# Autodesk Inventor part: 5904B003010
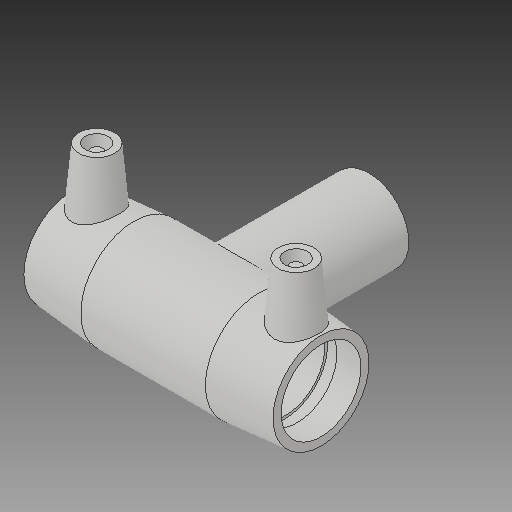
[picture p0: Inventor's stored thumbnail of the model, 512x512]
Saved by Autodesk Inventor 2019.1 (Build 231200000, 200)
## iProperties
Created: 2017-06
Part Number: 5904B003010
Material: Generic
Description: PLASSON TEE 1''IPS
Document SubType Name: Modeling
Designer: KIM
Mass: 17327.5 g
Surface Area: 12195.1 cm^2
Volume: 17327.5 cm^3
Density: 1 g/cm^3
Appearance: Default
Author: KIM
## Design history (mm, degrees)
derived "5904B.ipt"
feature "Solid1::5904B.ipt"
tag "TaggingFeature1"
body "Solid1"
other parameters: "d_" = 33.3, "L_" = 103.886, "L_1" = 37.592, "D_" = 44.45, "A_" = 42.672, "d_2" = 12, "H_" = 71.882, "d0" = 103.886, "d1" = 33.3, "d2" = 44.45, "d3" = 37.592, "d4" = 25.9715, "d5" = 40.005, "d6" = 31.635, "d7" = 33.3, "d8" = 168 deg, "d10" = 15.0368, "d11" = 5.01227, "d13" = 103.886, "d14" = 17.6296, "d17" = 29.97, "d18" = 33.3, "d19" = 3.52592, "d20" = 168 deg, "d22" = 41.3385, "d23" = 44.45, "d24" = 40.09835, "d25" = 135 deg, "d26" = 72.7202, "d27" = 135 deg, "d29" = 42.672, "d30" = 15, "d31" = 41.5544, "d34" = 5 deg, "d35" = 15, "d39" = 5 deg, "d40" = 9.6, "d41" = 4.8, "d42" = 6, "d43" = 0, "d45" = 4, "d46" = 14, "d47" = 0, "d48" = -71.882, "d49" = 33.3, "d51" = 0, "d52" = 26.64, "d54" = 0, "d55" = 40.005, "d56" = 44.45, "d57" = 36.3601, "d58" = 135 deg, "d59" = 37.592, "d60" = 37.592, "d61" = 135 deg, "d62" = 71.882, "d72" = 47.26813, "d73" = 23.63406, "d74" = -71.882, "d75" = 34.965, "d77" = 0, "d78" = 26.64, "d80" = 0, "d81" = 33.3, "d82" = 49.657, "d83" = 0, "d84" = 3, "d85" = 0, "d86" = 3, "d87" = 0, "d88" = 10.90168, "d89" = 2.72542, "d90" = 10.90168
